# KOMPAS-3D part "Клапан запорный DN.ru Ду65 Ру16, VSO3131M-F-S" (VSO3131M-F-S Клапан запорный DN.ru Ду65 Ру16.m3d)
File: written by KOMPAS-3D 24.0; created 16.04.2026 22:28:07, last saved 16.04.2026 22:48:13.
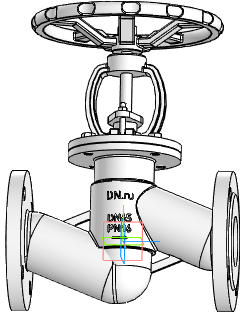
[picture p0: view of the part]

Document properties: Автор: R2D2; Полное имя файла: E:\Работа\Зайцев\VSO3131M-F-S Клапан запорный DN.ru Ду15-100 Ру16\DN65\VSO3131M-F-S Клапан запорный DN.ru Ду65 Ру16.m3d

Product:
- Part/product: Клапан запорный DN.ru Ду65 Ру16  | designation VSO3131M-F-S
    Масса: 16
    Раздел спецификации: Прочие изделия
    Примечание: D090-02952

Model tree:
1. Операция без истории:2

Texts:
  VSO3131M-F-S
